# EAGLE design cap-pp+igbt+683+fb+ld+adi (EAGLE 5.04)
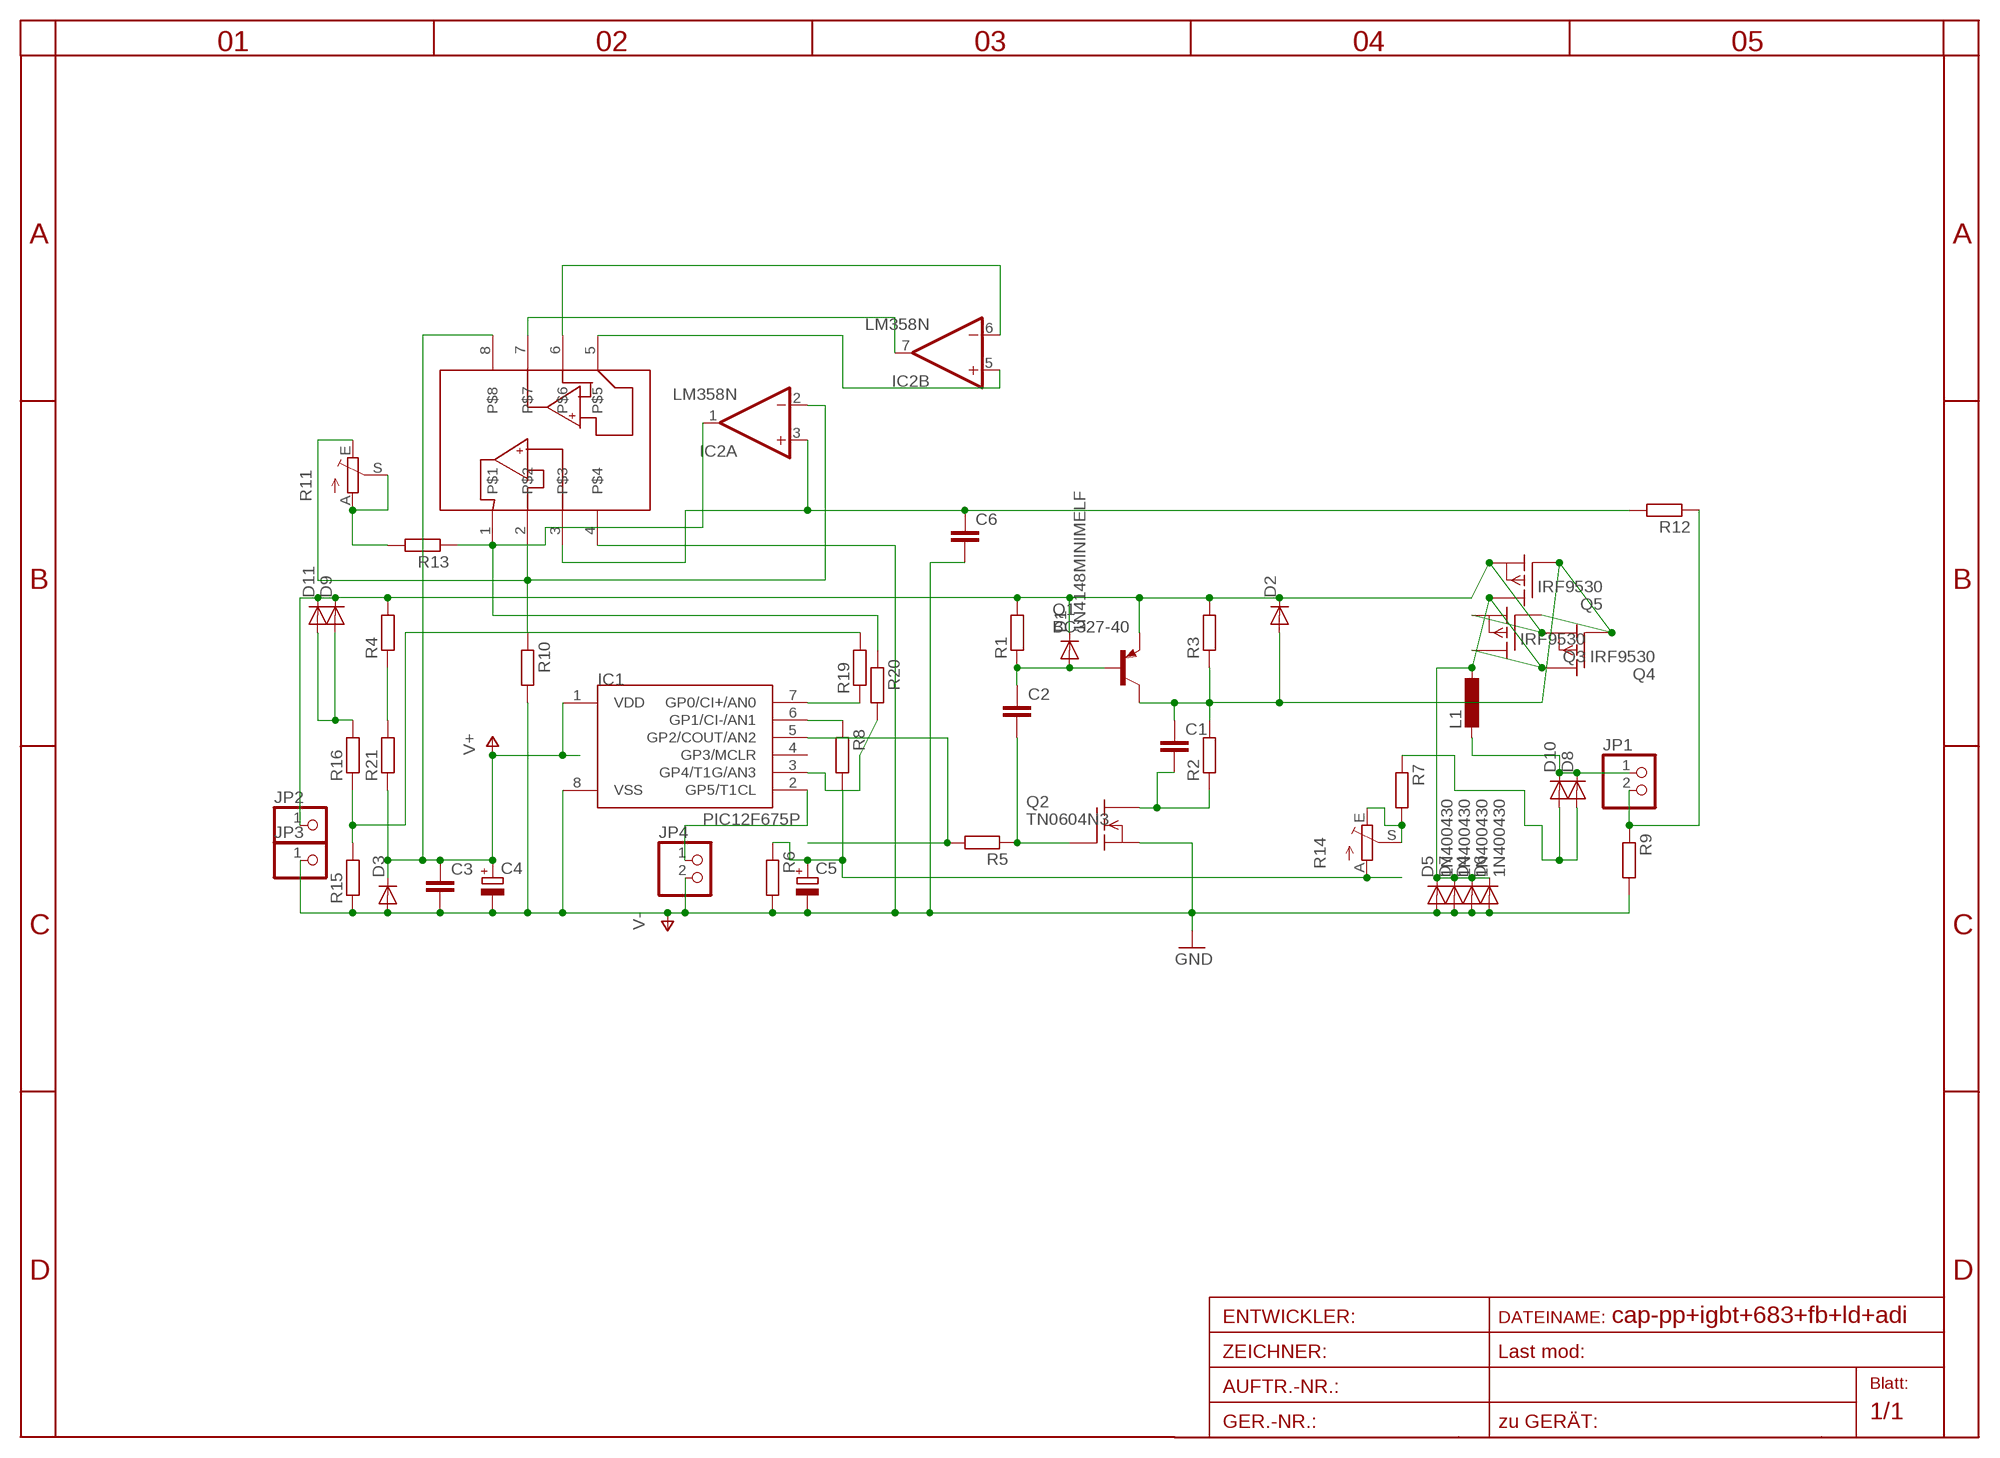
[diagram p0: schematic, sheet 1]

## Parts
C1  C-EU225-074X268  [C225-074X268]
C2  C-EU225-062X268  [C225-062X268]
C3  C-EU050-025X075  [C050-025X075]
C4  CPOL-EU5-13  [2,5-5-FLAT]
C5  CPOL-EU5-13  [2,5-5-FLAT]
C6  C-EU025_050-025X075  [C025_050-025X075]
D1  1N4148MINIMELF  [MINIMELF]
D2  DIODE-D-5  [D-5]
D3  DIODE-D-2.5  [D-2.5]
D4  1N400430  [DO41-30]
D5  1N400430  [DO41-30]
D6  1N400430  [DO41-30]
D7  1N400430  [DO41-30]
D8  DIODE-D-2.5  [D-2.5]
D9  DIODE-D-2.5  [D-2.5]
D10  DIODE-DO41-30  [DO41-30]
D11  DIODE-DO41-30  [DO41-30]
IC1  PIC12F675P  [DIL8]
IC2  LM358N  [DIL08]
JP1  PINHD-1X2  [1X02]
JP2  PINHD-1X1  [1X01]
JP3  PINHD-1X1  [1X01]
JP4  PINHD-1X2  [1X02]
L1  L-EU0204/7  [0204/7]
Q1  BC327-40  [TO92-EBC]
Q2  TN0604N3  [TO-92]
Q3  IRF9530  [TO220]
Q4  IRF9530  [TO220]
Q5  IRF9530  [TO220]
R1  R-EU_0204/2V  [0204V]
R2  R-EU_0207/25  [0207/25]
R3  R-EU_0204/2V  [0204V]
R4  R-EU_0207/10  [0207/10]
R5  R-EU_0207/40  [0207/40]
R6  R-EU_0204/5  [0204/5]
R7  R-EU_0207/15  [0207/15]
R8  R-EU_0207/10  [0207/10]
R9  R-EU_0617/22  [0617/22]
R10  R-EU_0207/15  [0207/15]
R11  TRIM_EU-CIP20C-4MM  [CIP20C-4MM]
R12  R-EU_0207/30  [0207/30]
R13  R-EU_0207/40  [0207/40]
R14  TRIM_EU-CIP20C-4MM  [CIP20C-4MM]
R15  R-EU_0204/5  [0204/5]
R16  R-EU_0207/25  [0207/25]
R19  R-EU_0204/5  [0204/5]
R20  R-EU_0204/5  [0204/5]
R21  R-EU_0207/10  [0207/10]
U$1  MCP6042SOIC  [SO-08]

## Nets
BB: C2.2 Q2.2(G) R5.1
DRAIN: D4.C D5.C D6.C D7.C L1.1 Q3.2(D) Q4.2(D) Q5.2(D)
GATE: C1.1 D2.A Q1.C Q3.1(G) Q4.1(G) Q5.1(G) R2.2 R3.1
MPOINT: C5.+ R6.1 R8.2 R14.A
N$1: C1.2 Q2.3(D) R2.1
N$2: IC2.6(B:-IN) U$1.6
N$3: IC1.5(GP2/COUT/AN2) R5.2
N$4: R4.1 R21.2
N$5: IC1.6(GP1/CI-/AN1) R8.1
N$6: IC2.2(A:-IN) R10.1 R11.E U$1.2
N$7: IC2.1(A:OUT) R13.1 R20.1 U$1.1
N$8: C6.1 IC2.3(A:+IN) R12.2 U$1.3
N$9: R11.A R11.S R13.2
N$10: R7.2 R14.E R14.S
N$12: R15.2 R16.1 R19.2
N$13: D9.A D11.A R16.2
N$14: IC1.7(GP0/CI+/AN0) R19.1
N$15: IC1.2(GP5/T1CL) JP4.1
N$16: D8.A D10.A R7.1
N$17: IC1.3(GP4/T1G/AN3) R20.2
N$18: IC2.5(B:+IN) U$1.5
N$20: IC2.7(B:OUT) U$1.7
OUT+: D8.C D10.C JP1.1 L1.2
OUT-: JP1.2 R9.1 R12.1
TB: C2.1 D1.A Q1.B R1.1
V+: C3.1 C4.+ D3.C IC1.1(VDD) R21.1 U$1.8
V-: C3.2 C4.- C5.- C6.2 D3.A D4.A D5.A D6.A D7.A IC1.8(VSS) JP3.1 JP4.2 Q2.1(S) R6.2 R9.2 R10.2 R15.1 U$1.4 ; supply symbol labelled GND
VIN: D1.C D2.C D9.C D11.C JP2.1 Q1.E Q3.3(S) Q4.3(S) Q5.3(S) R1.2 R3.2 R4.2
Unconnected: IC1.4(GP3/MCLR)

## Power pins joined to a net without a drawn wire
V+: IC2.8(P:V+)
V-: IC2.4(P:V-)

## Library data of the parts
C1-C3 C6 = rcl-2:C-EU: CAPACITOR, European symbol
C4 C5 = rcl-2:CPOL-EU: POLARIZED CAPACITOR, European symbol
D1 = diode-1:1N4148: DIODE
D2 D3 D8-D11 = diode-1:DIODE-: DIODE
D4-D7 = diode-1:1N4004: DIODE
IC1 = microchip-5:PIC12F6*: uPC nW 1k Program Flash memory 2x Timer Comparator 10b A/D converter/ 4xIN
IC2 = linear:LM358: OP AMP also LM158; LM258; LM2904 Source: http://cache.national.com/ds/LM/LM158.pdf
JP1 JP4 = pinhead:PINHD-1X2: PIN HEADER
JP2 JP3 = pinhead:PINHD-1X1: PIN HEADER
L1 = rcl-2:L-EU: INDUCTOR, European symbol
Q1 = transistor-pnp:BC327*: PNP Transistror
Q2 = transistor-fet:TN0604N3: N-Channel Enhancement MOSFET 40V; 4A; 0,75Ohm
Q3-Q5 = transistor-fet:IRF9530: P-Channel Enhancement MOSFET (HEXFET); -100V; -12A; 0,3Ohm
R1-R10 R12 R13 R15 R16 R19-R21 = rcl-2:R-EU_: RESISTOR, European symbol
R11 R14 = pot:TRIM_EU-: POTENTIOMETER
U$1 = microchip-3:MCP6042

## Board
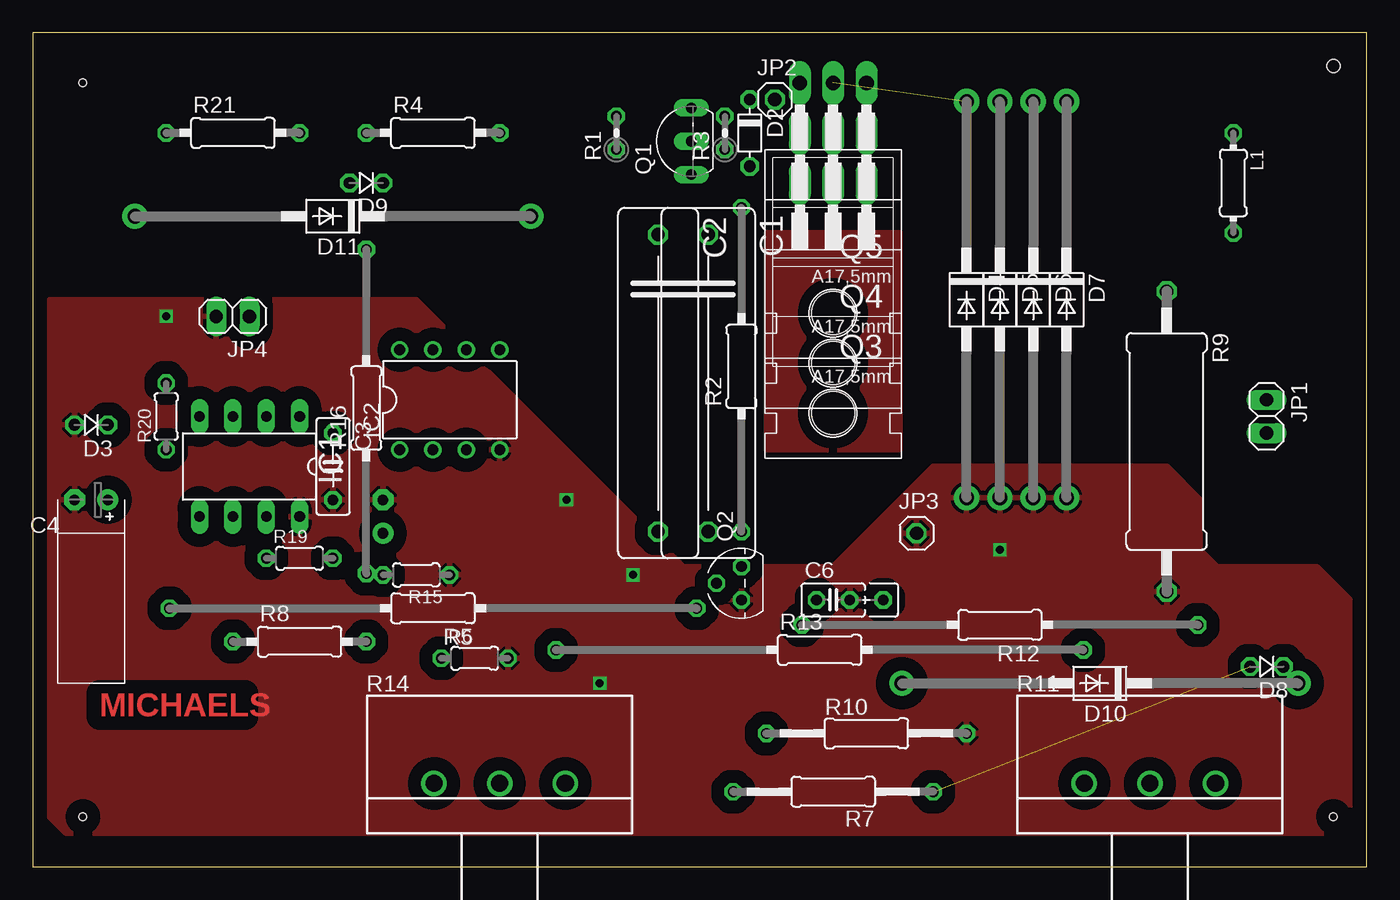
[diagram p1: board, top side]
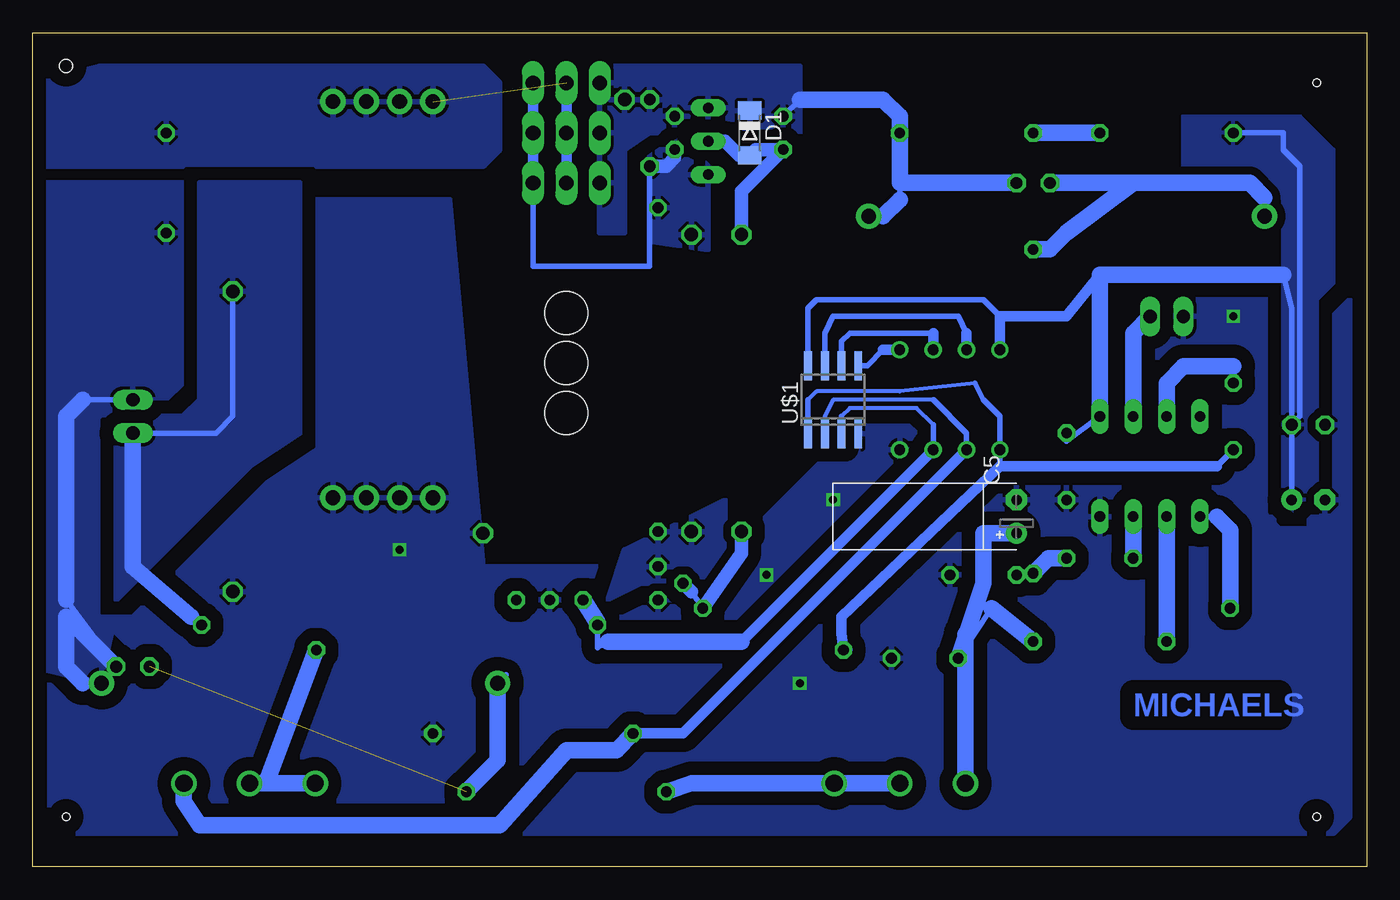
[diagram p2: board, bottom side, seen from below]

Size 101.6 x 63.5 mm. Coordinates in mm from the lower left corner, seen from the top.
Outline: 0,0 101.6,0 101.6,63.5 0,63.5 0,0
Copper layers (1*16): Top 0.035mm / dielectric 1.5mm / Bottom 0.035mm
Design rules "default": minimum track width 10mil, minimum drill 24mil, track to track 8mil, track to pad 8mil, pad to pad 8mil, via to via 8mil, smd to smd 8mil, copper to edge 40mil, drill to drill 8mil, minimum pad ring 10mil, minimum via ring 8mil, stop-mask expansion 4mil, vias tented up to drill 0mil, thermal gap 10mil
Holes 0.6 mm at 3.81,59.69 3.81,3.81 99.06,3.81
Holes 1 mm at 99.06,60.96

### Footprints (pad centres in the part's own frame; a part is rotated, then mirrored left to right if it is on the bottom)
C225-074X268 = drill 1.016 octagon: 1 -11.303,0; 2 11.303,0
C225-062X268 = drill 1.016 octagon: 1 -11.303,0; 2 11.303,0
C050-025X075 = drill 0.813 octagon: 1 -2.54,0; 2 2.54,0
2,5-5-FLAT = drill 0.813 pad 1.6 round: + -1.27,0 | drill 0.813 pad 1.6 octagon: - 1.27,0
C025_050-025X075 = drill 0.813 octagon: 1 -1.27,0; 2 1.27,0; 3 3.81,0
MINIMELF = smd 1.4 x 1.8: A 1.7,0; C -1.7,0
D-5 = drill 0.9 octagon: A 2.54,0; C -2.54,0
D-2.5 = drill 0.9 octagon: A 1.27,0; C -1.27,0
DO41-30 = drill 1.118 pad 1.93 round: A 15.08,0; C -15.08,0
DIL8 = drill 0.813 long: 1 -3.81,-3.81; 2 -1.27,-3.81; 3 1.27,-3.81; 4 3.81,-3.81; 5 3.81,3.81; 6 1.27,3.81; 7 -1.27,3.81; 8 -3.81,3.81
DIL08 = drill 0.813 pad 1.27 round: 1 -3.81,-3.81; 2 -1.27,-3.81; 3 1.27,-3.81; 4 3.81,-3.81; 5 3.81,3.81; 6 1.27,3.81; 7 -1.27,3.81; 8 -3.81,3.81
1X02 = drill 1.016 long: 1 -1.27,0; 2 1.27,0
1X01 = drill 1.016 octagon: 1 0,0
0204/7 = drill 0.813 octagon: 1 -3.81,0; 2 3.81,0
TO92-EBC = drill 0.813 long: B 0,-1.27; C -2.54,-1.27; E 2.54,-1.27
TO-92 = drill 0.813 octagon: 1 -1.27,0; 2 0,1.905; 3 1.27,0
TO220 = drill 1.118 long: 1 -2.54,-6.35; 2 0,-6.35; 3 2.54,-6.35 | hole 3.302: 0,11.176
0204V = drill 0.813 octagon: 1 -1.27,0; 2 1.27,0
0207/25 = drill 0.813 octagon: 1 -12.58,0; 2 12.08,0
0207/10 = drill 0.813 octagon: 1 -5.08,0; 2 5.08,0
0207/40 = drill 0.813 octagon: 1 -20.08,0; 2 20.08,0
0204/5 = drill 0.813 octagon: 1 -2.54,0; 2 2.54,0
0207/15 = drill 0.813 octagon: 1 -7.62,0; 2 7.62,0
0617/22 = drill 1.016 octagon: 1 -11.43,0; 2 11.43,0
CIP20C-4MM = drill 1.3 pad 1.93 round: A -5,0; E 5,0; S 0,0
0207/30 = drill 0.813 octagon: 1 -15.08,0; 2 15.08,0
SO-08 = smd 0.6 x 2.2: 1 -1.905,-2.6; 2 -0.635,-2.6; 3 0.635,-2.6; 4 1.905,-2.6; 5 1.905,2.6; 6 0.635,2.6; 7 -0.635,2.6; 8 -1.905,2.6

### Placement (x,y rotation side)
C1  51.44,36.83 270 top
C2  47.62,36.83 270 top
C3  22.86,30.48 270 top
C4  4.45,27.94 180 top
C5  26.67,26.67 90 bottom
C6  60.96,20.32 0 top
D1  46.99,55.88 270 bottom
D2  54.61,55.88 270 top
D3  4.45,33.66 180 top
D4  71.12,43.18 270 top
D5  73.66,43.18 270 top
D6  76.2,43.18 270 top
D7  78.74,43.18 270 top
D8  93.98,15.24 180 top
D9  25.4,52.07 180 top
D10  81.28,13.97 180 top
D11  22.86,49.53 180 top
IC1  16.51,30.48 180 top
IC2  31.75,35.56 0 top
JP1  93.98,34.29 270 top
JP2  56.52,58.42 0 top
JP3  67.31,25.4 0 top
JP4  15.24,41.91 180 top
L1  91.44,52.07 270 top
Q1  48.9,55.24 90 top
Q2  53.98,21.59 90 top
Q3  60.96,45.72 180 top
Q4  60.96,49.53 180 top
Q5  60.96,53.34 180 top
R1  44.45,55.88 90 top
R2  53.98,38.1 90 top
R3  52.7,55.88 90 top
R4  30.48,55.88 0 top
R5  30.48,19.68 180 top
R6  33.66,15.88 0 top
R7  60.96,5.71 180 top
R8  20.32,17.14 0 top
R9  86.36,32.38 270 top
R10  63.5,10.16 0 top
R11  85.09,6.35 0 top
R12  73.66,18.41 180 top
R13  59.93,16.51 0 top
R14  35.56,6.35 0 top
R15  29.21,22.23 180 top
R16  25.4,34.92 90 top
R19  20.32,23.5 0 top
R20  10.16,34.29 90 top
R21  15.24,55.88 0 top
U$1  40.64,35.56 0 bottom

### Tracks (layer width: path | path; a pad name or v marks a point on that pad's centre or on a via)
BB
  Bottom 0.406: R5.1 51.44,20.95
  Bottom 1.016: C2.2 47.62,23.89 R5.1 | 51.44,20.95 Q2.2
DRAIN  (1 unrouted)
  Bottom 0.813: Q3.2 Q4.2 Q5.2
  pour Top (isolate 0.813, rank 4): 66.04,48.26 66.04,31.75 55.88,31.75 55.88,48.26
  pour Bottom (isolate 1.016, rank 5): 66.04,59.69 67.31,60.96 96.52,60.96 101.6,59.69 101.6,53.34 67.31,53.34 66.04,54.61
GATE
  Bottom 0.406: D2.A 54.61,45.72 63.5,45.72 Q3.1
  Bottom 0.813: Q3.1 Q4.1 Q5.1
  Bottom 1.016: R3.1 52.7,53.98 53.34,53.34 D2.A
  pour Bottom (isolate 0.813, rank 3): 50.16,53.34 52.7,55.88 54.61,54.61 54.61,47.62 50.16,46.99
MPOINT
  Bottom 0.406: 28.57,19.68 R6.1 30.56,17.7
  Bottom 1.27: 28.57,19.68 R8.2 | R14.A 30.56,17.7 | R6.1 29.21,21.59 29.21,25.4 C5.+
N$1
  pour Bottom (isolate 0.61, rank 3): 48.9,27.94 56.52,24.13 57.78,20.32 55.24,21.59 48.9,21.59
N$2
  Bottom 0.406: U$1.6 40.01,40.01 39.37,40.64 33.02,40.64
  Bottom 0.813: IC2.6 33.02,40.64
N$3
  Bottom 0.406: 11.43,26.67 IC1.5
  Bottom 1.27: R5.2 10.4,25.64 11.43,26.67
N$4
  Bottom 1.27: R21.2 R4.1
N$5
  Bottom 1.27: R8.1 IC1.6
N$6
  Bottom 0.305: U$1.2 41.27,34.29 40.64,35.56 33.02,35.56
  Bottom 0.406: 33.02,35.56 30.48,33.02 IC2.2
  Bottom 0.813: R10.1 52.07,10.16 IC2.2
  Bottom 1.27: R11.E 90.09,5 88.9,3.17 66.04,3.17 60.96,8.89 57.15,8.89 R10.1
N$7
  Bottom 0.305: 29.84,36.83 35.56,36.2 41.91,36.2 42.55,35.56
  Bottom 0.406: 29.84,36.83 29.21,35.56 27.94,34.29 IC2.1 27.94,30.48 | 42.55,35.56 U$1.1 | R13.1 39.37,16.51 | R20.1 11.43,30.48
  Bottom 0.813: 11.43,30.48 27.94,30.48 40.01,19.05 40.01,17.78 R13.1
N$8
  Bottom 0.305: 33.02,33.66 34.29,34.92 39.37,34.92 40.01,34.29
  Bottom 0.406: 57.78,17.14 58.58,16.67 R12.2 58.58,18.57 | IC2.3 33.02,33.66 | 40.01,34.29 U$1.3
  Bottom 0.813: 47.62,17.14 IC2.3
  Bottom 1.27: 47.62,17.14 57.78,17.14 | 58.58,18.57 C6.1
N$9
  Bottom 0.406: R11.S 83.82,6.35
  Bottom 1.27: 83.82,6.35 R13.2 | R11.A R11.S
N$10
  Bottom 1.27: R14.S R14.E 51.44,6.35 R7.2
N$12
  Bottom 0.406: R15.2 25.52,22.23 R16.1
  Bottom 1.27: R19.2 24.25,23.5 R16.1
N$13
  Bottom 0.406: D11.A 7.78,50.96
  Bottom 1.27: 7.78,50.96 8.89,52.07 17.78,52.07 | 17.78,52.07 D9.A | R16.2 24.11,47.01 22.86,48.26 17.78,52.07
N$14
  Bottom 1.27: R19.1 IC1.7
N$15
  Bottom 1.27: IC1.2 17.78,40.64 JP4.1
N$16  (1 unrouted)
  Bottom 0.406: D10.A 65.56,14.61
  Bottom 1.27: D10.A 66.2,8.1 R7.1
N$17
  Bottom 0.406: R20.2 10.16,38.1
  Bottom 1.27: 10.16,38.1 13.97,38.1 15.24,36.83 IC1.3
N$18
  Bottom 0.406: U$1.5 38.04,38.16 36.83,39.37
  Bottom 0.813: IC2.5 36.83,39.37
N$20
  Bottom 0.406: U$1.7 41.27,40.64 40.64,41.91 31.11,41.91 30.48,40.64
  Bottom 0.813: IC2.7 30.48,40.64
OUT+
  Bottom 0.406: 97.79,35.56 JP1.1 | D8.C 99.06,20.32 | D10.C 97.79,13.97
  Bottom 1.27: 97.79,35.56 99.06,34.29 99.06,20.32 | D8.C 99.06,19.05 99.06,15.24 97.79,13.97
  pour Bottom (isolate 1.016, rank 5): 88.9,52.07 101.6,52.07 101.6,15.24 96.52,13.97 91.44,35.56 90.17,36.83
OUT-
  Bottom 0.406: R12.1 89.53,19.05 | JP1.2 87.63,33.02 86.36,34.29 R9.1
  Bottom 1.27: 89.53,19.05 93.98,22.86 JP1.2
  pour Bottom (isolate 1.016, rank 4): 81.28,52.07 88.9,52.07 88.9,35.56 90.17,34.29 93.98,34.29 95.25,33.02 95.25,20.32 85.09,30.48 81.28,33.02
TB
  Bottom 1.016: C2.1 47.62,51.44 R1.1 46.56,54.61 D1.A 47.83,54.18 48.9,55.24 Q1.B
V+
  Bottom 0.406: R21.1 6.35,55.88 6.35,54.61 5.08,53.34 5.08,34.29 D3.C | D3.C 5.71,42.55 6.35,45.09 | IC1.1 22.86,32.38 C3.1 | U$1.8 42.55,42.55 41.91,43.18 29.21,43.18 27.94,41.91 | C4.+ D3.C
  Bottom 0.813: 20.32,45.09 22.86,41.91 27.94,41.91 IC2.8
  Bottom 1.27: 6.35,45.09 20.32,45.09 IC1.1
  pour Bottom (isolate 0.61, rank 3): 13.97,57.15 5.08,57.15 2.54,54.61 2.54,44.45 3.81,43.18 3.81,27.94 5.08,26.67 6.35,27.94 6.35,50.8 8.89,53.34 13.97,53.34
V-  (via drill 0.6)
  other vias: 40.64,27.94 45.72,22.23 43.18,13.97 73.66,24.13 10.16,41.91
  pour Bottom (isolate 1.016, rank 5): 1.27,43.18 29.21,43.18 49.53,22.86 67.31,22.86 69.85,50.8 85.09,50.8 88.9,27.94 88.9,24.13 90.17,22.86 97.79,22.86 100.33,20.32 100.33,3.81 99.06,2.54 2.54,2.54 1.27,3.81
  pour Top (isolate 1.016, rank 5): 1.27,43.18 29.21,43.18 49.53,22.86 60.96,22.86 68.58,30.48 86.36,30.48 88.9,27.94 88.9,24.13 90.17,22.86 97.79,22.86 100.33,20.32 100.33,3.81 99.06,2.54 2.54,2.54 1.27,3.81
VIN
  Bottom 0.406: 43.18,58.42 R1.2 | 35.56,52.07 35.56,50.8 | 36.83,49.53 D11.C
  Bottom 1.27: 43.18,58.42 36.83,58.42 35.56,57.15 R4.2 35.56,52.07 D9.C | 35.56,50.8 36.83,49.53
  pour Bottom (isolate 1.016, rank 2): 43.18,55.88 54.61,55.88 56.52,54.61 56.52,48.26 58.42,48.26 58.42,60.96 43.18,60.96

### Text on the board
Top: MICHAELS
Bottom: MICHAELS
